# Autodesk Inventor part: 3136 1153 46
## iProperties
Shininess: 60.0
Length Units: 11269
Angle Units: 11279
Time Units: 11290
Mass Units: 11283
Length Display Precision: 3
Angle Display Precision: 2
Compacted: True
Created: 2000-11
Part Number: 3136 1153 46
Material: Steel, Mild
Description: Plate
Document SubType Name: Sheet Metal
Designer: Joe M
Engineer: Joe M
Density: 7.859999999999999
Volumn: 388.5819073469936
Area: 2023.5982947331645
PropertySet Name: Model Information
Control State: 0
Master: False
Checked Out: False
Last Check In By: koman
Last Check In Date: 2001-11-27
Title: Sidoplåt vänster
Author: Joe M
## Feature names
1. Cut2
2. Cut3
3. Corner Round6
4. Extrusion8
5. Extrusion9
6. Extrusion10
7. Extrusion11
8. Extrusion13
9. Extrusion14
10. Extrusion15
11. Fillet2
12. Fillet3
13. Hole4
14. FlatPatternExtrusion1
15. Extrusion12
